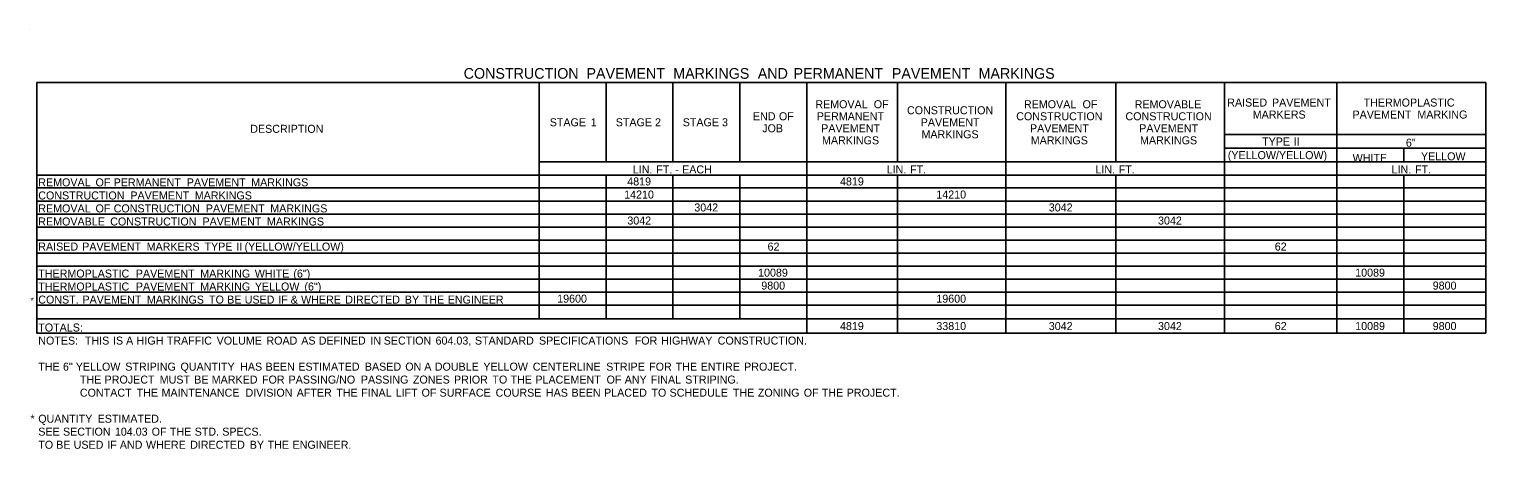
# Model space of a CAD drawing. Extents: x 977434 to 989596, y 1525697 to 1528336.
# Drawn here: x 979085 to 980177, y 1525714 to 1526028 of the extents above; entities that cross this region are included whole.
import ezdxf

# ---------------------------------------------------------------- set-up
doc = ezdxf.new("R2010")
doc.units = 0
doc.layers.add('Default', color=7, linetype='Continuous')
doc.layers.add('R_Border Prem', color=7, linetype='Continuous')

msp = doc.modelspace()

# ---------------------------------------------------------------- linework, layer by layer
at = {"layer": 'Default'}
for p, q in [((979090.8, 1525988.2), (980177, 1525988.2)), ((979090.8, 1525800.5), (979090.8, 1525988.2)), ((979090.8, 1525800.5), (979090.8, 1525988.2)), ((979467.2, 1525811.2), (979467.2, 1525988.2)), ((979517.4, 1525928.7), (979517.4, 1525988.2)), ((979567.6, 1525928.7), (979567.6, 1525988.2)), ((979617.8, 1525928.7), (979617.8, 1525988.2)), ((979668, 1525800.5), (979668, 1525988.2)), ((979735.8, 1525928.7), (979735.8, 1525988.2)), ((979817.2, 1525800.5), (979817.2, 1525988.2)), ((979899.6, 1525928.7), (979899.6, 1525988.2)), ((979981, 1525800.5), (979981, 1525988.2)), ((979981, 1525949.2), (979981, 1525988.2)), ((980065.3, 1525800.5), (980065.3, 1525988.2)), ((980177, 1525800.5), (980177, 1525988.2)), ((980177, 1525800.5), (980177, 1525988.2)), ((979981, 1525949.2), (980177, 1525949.2)), ((979467.2, 1525928.7), (980177, 1525928.7)), ((979981, 1525938.9), (980177, 1525938.9)), ((979981, 1525800.5), (979981, 1525928.7)), ((980065.3, 1525800.5), (980065.3, 1525928.7)), ((980115.5, 1525928.7), (980115.5, 1525938.9)), ((979090.8, 1525918.9), (980177, 1525918.9)), ((979467.2, 1525811.2), (979467.2, 1525918.9)), ((979517.4, 1525811.2), (979517.4, 1525918.9)), ((979517.4, 1525811.2), (979517.4, 1525918.9)), ((979567.6, 1525811.2), (979567.6, 1525918.9)), ((979567.6, 1525811.2), (979567.6, 1525918.9)), ((979617.8, 1525811.2), (979617.8, 1525918.9)), ((979617.8, 1525811.2), (979617.8, 1525918.9)), ((979668, 1525800.5), (979668, 1525918.9)), ((979735.8, 1525800.5), (979735.8, 1525918.9)), ((979735.8, 1525800.5), (979735.8, 1525918.9)), ((979817.2, 1525800.5), (979817.2, 1525918.9)), ((979899.6, 1525800.5), (979899.6, 1525918.9)), ((979899.6, 1525800.5), (979899.6, 1525918.9)), ((980115.5, 1525800.5), (980115.5, 1525918.9)), ((980115.5, 1525800.5), (980115.5, 1525918.9)), ((979090.8, 1525909.2), (980177, 1525909.2)), ((979090.8, 1525899.4), (980177, 1525899.4)), ((979090.8, 1525889.7), (980177, 1525889.7)), ((979090.8, 1525879.9), (980177, 1525879.9)), ((979090.8, 1525870.2), (980177, 1525870.2)), ((979090.8, 1525860.4), (980177, 1525860.4)), ((979090.8, 1525850.7), (980177, 1525850.7)), ((979090.8, 1525840.9), (980177, 1525840.9)), ((979090.8, 1525831.2), (980177, 1525831.2)), ((979090.8, 1525821.4), (980177, 1525821.4)), ((979090.8, 1525811.2), (980177, 1525811.2)), ((979090.8, 1525800.5), (980177, 1525800.5))]:
    msp.add_line(p, q, dxfattribs=at)
at = {"layer": 'R_Border Prem'}
msp.add_line((979085, 1526028.1), (979085, 1526028.1), dxfattribs=at)

# ---------------------------------------------------------------- texts
at = {"layer": 'Default'}
for s, height, p in [('CONSTRUCTION', 8, (979410.7, 1525991)), (' PAVEMENT', 8, (979499.8, 1525991)), (' MARKINGS', 8, (979564.8, 1525991)), (' AND', 8, (979628.2, 1525991)), (' PERMANENT', 8, (979655, 1525991)), (' PAVEMENT', 8, (979728.7, 1525991)), (' MARKINGS', 8, (979793.7, 1525991)), ('REMOVAL', 6, (979674.3, 1525968.9)), (' OF', 6, (979715.9, 1525968.9)), ('REMOVAL', 6, (979830.7, 1525968.9)), (' OF', 6, (979872.4, 1525968.9)), ('REMOVABLE', 6, (979913.7, 1525968.9)), ('RAISED', 6, (979983.1, 1525970.2)), (' PAVEMENT', 6, (980014.4, 1525970.2)), ('THERMOPLASTIC', 6, (980085.3, 1525970.2)), ('STAGE', 6, (979475.2, 1525955.4)), (' 1', 6, (979503.7, 1525955.4)), ('STAGE 2', 6, (979524.7, 1525955.4)), ('STAGE 3', 6, (979574.9, 1525955.4)), ('END', 6, (979627.5, 1525959.9)), (' OF', 6, (979644.8, 1525959.9)), ('PERMANENT', 6, (979675.4, 1525959.9)), ('CONSTRUCTION', 6, (979743, 1525964.4)), ('PAVEMENT', 6, (979753.3, 1525955.4)), ('CONSTRUCTION', 6, (979824.9, 1525959.9)), ('CONSTRUCTION', 6, (979906.8, 1525959.9)), ('MARKERS', 6, (980002.2, 1525961.2)), ('PAVEMENT', 6, (980077, 1525961.2)), (' MARKING', 6, (980123.4, 1525961.2)), ('DESCRIPTION', 6, (979250.7, 1525950.5)), ('JOB', 6, (979634.5, 1525950.9)), ('PAVEMENT', 6, (979678.7, 1525950.9)), ('MARKINGS', 6, (979753.9, 1525946.4)), ('PAVEMENT', 6, (979835.2, 1525950.9)), ('PAVEMENT', 6, (979917.1, 1525950.9)), ('MARKINGS', 6, (979679.3, 1525941.9)), ('MARKINGS', 6, (979835.8, 1525941.9)), ('MARKINGS', 6, (979917.7, 1525941.9)), ('TYPE', 6, (980009.2, 1525941)), (' II', 6, (980030.7, 1525941)), ('6"', 6, (980117, 1525940.1)), ('(YELLOW/YELLOW)', 6, (979983.5, 1525930.8)), ('WHITE', 6, (980077.1, 1525928.7)), ('YELLOW', 6, (980128.3, 1525929.9)), ('4819', 6, (979533.3, 1525911.1)), ('LIN.', 6, (979537.5, 1525920.1)), (' FT.', 6, (979552.8, 1525920.1)), (' -', 6, (979567.1, 1525920.1)), (' EACH', 6, (979572.2, 1525920.1)), ('4819', 6, (979692.8, 1525911.1)), ('LIN.', 6, (979727.8, 1525920.1)), (' FT.', 6, (979743.1, 1525920.1)), ('LIN.', 6, (979884.3, 1525920.1)), (' FT.', 6, (979899.5, 1525920.1)), ('LIN.', 6, (980106.3, 1525920.1)), (' FT.', 6, (980121.6, 1525920.1)), ('CONSTRUCTION', 6, (979091.8, 1525900.6)), ('REMOVAL', 6, (979091.8, 1525910.4)), (' OF', 6, (979132.5, 1525910.4)), (' PERMANENT', 6, (979146.1, 1525910.4)), (' PAVEMENT', 6, (979158.6, 1525900.6)), (' PAVEMENT', 6, (979200.9, 1525910.4)), (' MARKINGS', 6, (979206.9, 1525900.6)), (' MARKINGS', 6, (979249.2, 1525910.4)), ('14210', 6, (979531, 1525901.3)), ('14210', 6, (979765, 1525901.3)), ('REMOVAL', 6, (979091.8, 1525890.9)), (' OF', 6, (979132.5, 1525890.9)), (' CONSTRUCTION', 6, (979146.1, 1525890.9)), (' PAVEMENT', 6, (979215.2, 1525890.9)), (' MARKINGS', 6, (979263.5, 1525890.9)), ('3042', 6, (979583.6, 1525891.6)), ('3042', 6, (979849.3, 1525891.6)), ('REMOVABLE', 6, (979091.8, 1525881.1)), (' CONSTRUCTION', 6, (979143.5, 1525881.1)), (' PAVEMENT', 6, (979212.7, 1525881.1)), (' MARKINGS', 6, (979261, 1525881.1)), ('3042', 6, (979533.4, 1525881.8)), ('3042', 6, (979931.2, 1525881.8)), ('RAISED', 6, (979091.8, 1525862.3)), (' PAVEMENT', 6, (979122.5, 1525862.3)), (' MARKERS', 6, (979170.8, 1525862.3)), (' TYPE', 6, (979214.2, 1525862.3)), (' II', 6, (979238, 1525862.3)), (' (YELLOW/YELLOW)', 6, (979244.2, 1525862.3)), ('62', 6, (979638.5, 1525862.3)), ('62', 6, (980018.7, 1525862.3)), ('THERMOPLASTIC', 6, (979091.8, 1525842.1)), (' PAVEMENT', 6, (979162.7, 1525842.1)), (' MARKING', 6, (979211, 1525842.1)), (' WHITE', 6, (979251.9, 1525842.1)), (' (6")', 6, (979280.8, 1525842.1)), ('10089', 6, (979631.4, 1525842.8)), ('10089', 6, (980079, 1525842.8)), ('THERMOPLASTIC', 6, (979091.8, 1525832.4)), (' PAVEMENT', 6, (979162.7, 1525832.4)), (' MARKING', 6, (979211, 1525832.4)), (' YELLOW', 6, (979251.9, 1525832.4)), (' (6")', 6, (979289.1, 1525832.4)), ('9800', 6, (979633.8, 1525833.1)), ('9800', 6, (980137.1, 1525833.1)), ('*', 5, (979085.9, 1525822.4)), ('CONST.', 6, (979091.8, 1525822.6)), (' PAVEMENT', 6, (979122.7, 1525822.6)), (' MARKINGS', 6, (979171, 1525822.6)), (' TO', 6, (979217.6, 1525822.6)), (' BE', 6, (979231.2, 1525822.6)), (' USED', 6, (979244.3, 1525822.6)), (' IF', 6, (979269.5, 1525822.6)), (' &', 6, (979278.8, 1525822.6)), (' WHERE', 6, (979286.6, 1525822.6)), (' DIRECTED', 6, (979319.7, 1525822.6)), (' BY', 6, (979364.4, 1525822.6)), (' THE', 6, (979377.8, 1525822.6)), (' ENGINEER', 6, (979396.5, 1525822.6)), ('19600', 6, (979480.8, 1525823.3)), ('19600', 6, (979765, 1525823.3)), ('4819', 6, (979692.8, 1525802.8)), ('33810', 6, (979765, 1525802.8)), ('3042', 6, (979849.3, 1525802.8)), ('3042', 6, (979931.2, 1525802.8)), ('62', 6, (980018.7, 1525802.8)), ('10089', 6, (980079, 1525802.8)), ('9800', 6, (980137.1, 1525802.8)), ('TOTALS:', 6, (979091.8, 1525801.7)), ('NOTES:', 6, (979091.8, 1525791.9)), ('  THIS', 6, (979122.3, 1525791.9)), (' IS', 6, (979145.6, 1525791.9)), (' A', 6, (979155.4, 1525791.9)), (' HIGH', 6, (979163.3, 1525791.9)), (' TRAFFIC', 6, (979185.9, 1525791.9)), (' VOLUME', 6, (979223.3, 1525791.9)), (' ROAD', 6, (979260.6, 1525791.9)), (' AS', 6, (979286.7, 1525791.9)), (' DEFINED', 6, (979299.8, 1525791.9)), (' IN', 6, (979338.5, 1525791.9)), (' SECTION', 6, (979348.5, 1525791.9)), (' 604.03,', 6, (979387.4, 1525791.9)), (' STANDARD', 6, (979416.9, 1525791.9)), (' SPECIFICATIONS', 6, (979464.9, 1525791.9)), (' FOR', 6, (979536.7, 1525791.9)), (' HIGHWAY', 6, (979556.6, 1525791.9)), (' CONSTRUCTION.', 6, (979598.9, 1525791.9)), ('THE', 6, (979091.8, 1525772.4)), (' 6"', 6, (979108.1, 1525772.4)), (' YELLOW', 6, (979117.7, 1525772.4)), (' STRIPING', 6, (979154.8, 1525772.4)), (' QUANTITY', 6, (979196.2, 1525772.4)), (' HAS', 6, (979240.9, 1525772.4)), (' BEEN', 6, (979260, 1525772.4)), (' ESTIMATED', 6, (979284.5, 1525772.4)), (' BASED', 6, (979334.4, 1525772.4)), (' ON', 6, (979364.7, 1525772.4)), (' A', 6, (979378.9, 1525772.4)), (' DOUBLE', 6, (979386.8, 1525772.4)), (' YELLOW', 6, (979423.2, 1525772.4)), (' CENTERLINE', 6, (979460.3, 1525772.4)), (' STRIPE', 6, (979515.3, 1525772.4)), (' FOR', 6, (979547.5, 1525772.4)), (' THE', 6, (979567.4, 1525772.4)), (' ENTIRE', 6, (979586.1, 1525772.4)), (' PROJECT.', 6, (979618.7, 1525772.4)), ('THE', 6, (979123, 1525762.7)), (' PROJECT', 6, (979139.3, 1525762.7)), (' MUST', 6, (979180.6, 1525762.7)), (' BE', 6, (979206.5, 1525762.7)), (' MARKED', 6, (979219.6, 1525762.7)), (' FOR', 6, (979257.3, 1525762.7)), (' PASSING/NO', 6, (979277.2, 1525762.7)), (' PASSING', 6, (979331.4, 1525762.7)), (' ZONES', 6, (979370.4, 1525762.7)), (' PRIOR', 6, (979401.2, 1525762.7)), (' TO', 6, (979430, 1525762.7)), (' THE', 6, (979443.6, 1525762.7)), (' PLACEMENT', 6, (979462.2, 1525762.7)), (' OF', 6, (979515.6, 1525762.7)), (' ANY', 6, (979529.2, 1525762.7)), (' FINAL', 6, (979548.7, 1525762.7)), (' STRIPING.', 6, (979574.5, 1525762.7)), ('CONTACT', 6, (979123, 1525752.9)), (' THE', 6, (979163.3, 1525752.9)), (' MAINTENANCE', 6, (979182, 1525752.9)), (' DIVISION', 6, (979244.9, 1525752.9)), (' AFTER', 6, (979283.3, 1525752.9)), (' THE', 6, (979313, 1525752.9)), (' FINAL', 6, (979331.7, 1525752.9)), (' LIFT', 6, (979357.5, 1525752.9)), (' OF', 6, (979376.9, 1525752.9)), (' SURFACE', 6, (979390.4, 1525752.9)), (' COURSE', 6, (979432.4, 1525752.9)), (' HAS', 6, (979470.1, 1525752.9)), (' BEEN', 6, (979489.3, 1525752.9)), (' PLACED', 6, (979513.7, 1525752.9)), (' TO', 6, (979549.2, 1525752.9)), (' SCHEDULE', 6, (979562.8, 1525752.9)), (' THE', 6, (979610.3, 1525752.9)), (' ZONING', 6, (979629, 1525752.9)), (' OF', 6, (979663.4, 1525752.9)), (' THE', 6, (979676.9, 1525752.9)), (' PROJECT.', 6, (979695.6, 1525752.9)), ('*', 6, (979085.9, 1525733.4)), ('QUANTITY', 6, (979091.8, 1525733.4)), (' ESTIMATED.', 6, (979134.1, 1525733.4)), ('SEE', 6, (979091.8, 1525723.7)), (' SECTION', 6, (979108.1, 1525723.7)), (' 104.03', 6, (979147, 1525723.7)), (' OF', 6, (979174.6, 1525723.7)), (' THE', 6, (979188.2, 1525723.7)), (' STD.', 6, (979206.8, 1525723.7)), (' SPECS.', 6, (979227.5, 1525723.7)), ('TO', 6, (979091.8, 1525713.9)), (' BE', 6, (979103, 1525713.9)), (' USED', 6, (979116.1, 1525713.9)), (' IF', 6, (979141.3, 1525713.9)), (' AND', 6, (979150.7, 1525713.9)), (' WHERE', 6, (979170.3, 1525713.9)), (' DIRECTED', 6, (979203.4, 1525713.9)), (' BY', 6, (979248.1, 1525713.9)), (' THE', 6, (979261.5, 1525713.9)), (' ENGINEER.', 6, (979280.2, 1525713.9))]:
    msp.add_text(s, height=height, dxfattribs=at).set_placement(p)

doc.saveas('drawing.dxf')
